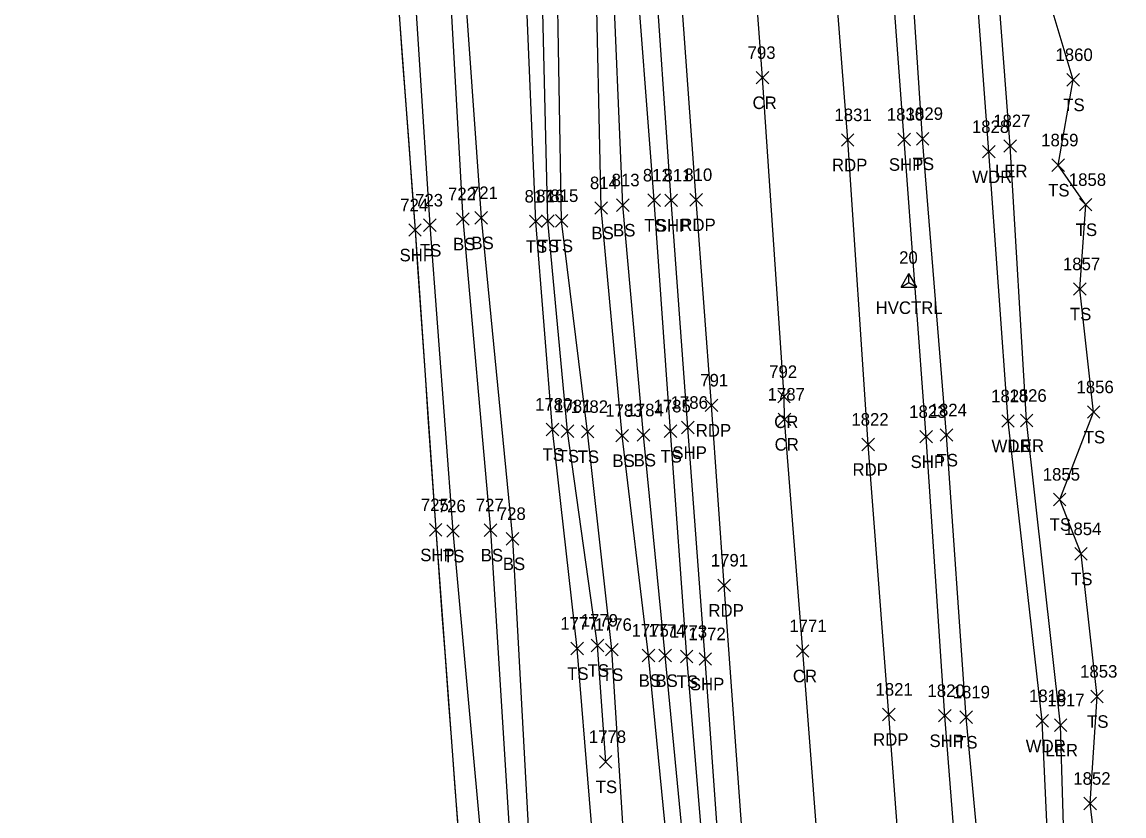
# Model space of a CAD drawing. Extents: x 1650221 to 1650634, y 244606 to 249996.
# Drawn here: x 1650345.8 to 1650521.6, y 244740.5 to 244867.1 of the extents above; entities that cross this region are included whole.
import ezdxf

# ---------------------------------------------------------------- set-up
doc = ezdxf.new("R2010")
doc.units = 0
for name, color, linetype in [('C_A', 7, 'Continuous'), ('C_I', 7, 'Continuous'), ('CPSM', 7, 'Continuous'), ('L_A', 7, 'Continuous'), ('L_I', 7, 'Continuous'), ('L_TIC', 7, 'Continuous'), ('LARO', 7, 'Continuous'), ('LAWA', 7, 'Continuous'), ('LELB', 7, 'Continuous'), ('LSOGP', 7, 'Continuous'), ('P_A', 7, 'Continuous'), ('P_I', 7, 'Continuous'), ('P_TIC', 7, 'Continuous'), ('PET', 7, 'Continuous'), ('PRC', 7, 'Continuous'), ('PSP', 7, 'Continuous')]:
    doc.layers.add(name, color=color, linetype=linetype)

msp = doc.modelspace()

# ---------------------------------------------------------------- linework, layer by layer
at = {"layer": 'CPSM'}
for p, q in [((1650485.99, 244824.86), (1650487.24, 244827.03)), ((1650488.49, 244824.86), (1650487.24, 244827.03)), ((1650487.24, 244825.58), (1650487.24, 244827.03)), ((1650485.99, 244824.86), (1650487.24, 244825.58)), ((1650485.99, 244824.86), (1650488.49, 244824.86)), ((1650487.24, 244825.58), (1650487.24, 244825.58)), ((1650487.24, 244825.58), (1650488.49, 244824.86))]:
    msp.add_line(p, q, dxfattribs=at)
at = {"layer": 'L_TIC'}
for points in [[(1650512.46, 244856.93), (1650514.46, 244858.93)], [(1650514.46, 244856.93), (1650512.46, 244858.93)], [(1650488.44, 244847.53), (1650490.44, 244849.53)], [(1650490.44, 244847.53), (1650488.44, 244849.53)], [(1650502.39, 244846.38), (1650504.39, 244848.38)], [(1650504.39, 244846.38), (1650502.39, 244848.38)], [(1650498.99, 244845.46), (1650500.99, 244847.46)], [(1650500.99, 244845.46), (1650498.99, 244847.46)], [(1650510.05, 244843.32), (1650512.05, 244845.32)], [(1650512.05, 244843.32), (1650510.05, 244845.32)], [(1650440.62, 244836.94), (1650442.62, 244838.94)], [(1650442.62, 244836.94), (1650440.62, 244838.94)], [(1650445.61, 244837.72), (1650447.61, 244839.72)], [(1650447.61, 244837.72), (1650445.61, 244839.72)], [(1650514.45, 244837.01), (1650516.45, 244839.01)], [(1650516.45, 244837.01), (1650514.45, 244839.01)], [(1650437.17, 244836.49), (1650439.17, 244838.49)], [(1650439.17, 244836.49), (1650437.17, 244838.49)], [(1650409.84, 244833.73), (1650411.84, 244835.73)], [(1650411.84, 244833.73), (1650409.84, 244835.73)], [(1650415.09, 244834.73), (1650417.09, 244836.73)], [(1650417.09, 244834.73), (1650415.09, 244836.73)], [(1650418.02, 244834.91), (1650420.02, 244836.91)], [(1650420.02, 244834.91), (1650418.02, 244836.91)], [(1650426.74, 244834.35), (1650428.74, 244836.35)], [(1650428.74, 244834.35), (1650426.74, 244836.35)], [(1650428.64, 244834.41), (1650430.64, 244836.41)], [(1650430.64, 244834.41), (1650428.64, 244836.41)], [(1650430.85, 244834.44), (1650432.85, 244836.44)], [(1650432.85, 244834.44), (1650430.85, 244836.44)], [(1650513.52, 244823.56), (1650515.52, 244825.56)], [(1650515.52, 244823.56), (1650513.52, 244825.56)], [(1650515.72, 244803.93), (1650517.72, 244805.93)], [(1650517.72, 244803.93), (1650515.72, 244805.93)], [(1650502.06, 244802.5), (1650504.06, 244804.5)], [(1650504.06, 244802.5), (1650502.06, 244804.5)], [(1650505.03, 244802.57), (1650507.03, 244804.57)], [(1650507.03, 244802.57), (1650505.03, 244804.57)], [(1650429.39, 244801.16), (1650431.39, 244803.16)], [(1650431.39, 244801.16), (1650429.39, 244803.16)], [(1650431.8, 244800.89), (1650433.8, 244802.89)], [(1650433.8, 244800.89), (1650431.8, 244802.89)], [(1650435, 244800.8), (1650437, 244802.8)], [(1650437, 244800.8), (1650435, 244802.8)], [(1650440.52, 244800.17), (1650442.52, 244802.17)], [(1650442.52, 244800.17), (1650440.52, 244802.17)], [(1650443.9, 244800.26), (1650445.9, 244802.26)], [(1650445.9, 244800.26), (1650443.9, 244802.26)], [(1650448.21, 244800.88), (1650450.21, 244802.88)], [(1650450.21, 244800.88), (1650448.21, 244802.88)], [(1650492.25, 244800.26), (1650494.25, 244802.26)], [(1650494.25, 244800.26), (1650492.25, 244802.26)], [(1650510.3, 244789.99), (1650512.3, 244791.99)], [(1650512.3, 244789.99), (1650510.3, 244791.99)], [(1650413.52, 244784.95), (1650415.52, 244786.95)], [(1650415.52, 244784.95), (1650413.52, 244786.95)], [(1650419.51, 244785.1), (1650421.51, 244787.1)], [(1650421.51, 244785.1), (1650419.51, 244787.1)], [(1650423.03, 244783.72), (1650425.03, 244785.72)], [(1650425.03, 244783.72), (1650423.03, 244785.72)], [(1650513.71, 244781.3), (1650515.71, 244783.3)], [(1650515.71, 244781.3), (1650513.71, 244783.3)], [(1650436.59, 244766.7), (1650438.59, 244768.7)], [(1650438.59, 244766.7), (1650436.59, 244768.7)], [(1650433.33, 244766.21), (1650435.33, 244768.21)], [(1650435.33, 244766.21), (1650433.33, 244768.21)], [(1650433.33, 244766.21), (1650435.33, 244768.21)], [(1650435.33, 244766.21), (1650433.33, 244768.21)], [(1650438.86, 244766.03), (1650440.86, 244768.03)], [(1650440.86, 244766.03), (1650438.86, 244768.03)], [(1650444.7, 244765.1), (1650446.7, 244767.1)], [(1650446.7, 244765.1), (1650444.7, 244767.1)], [(1650447.37, 244765.08), (1650449.37, 244767.08)], [(1650449.37, 244765.08), (1650447.37, 244767.08)], [(1650450.8, 244764.92), (1650452.8, 244766.92)], [(1650452.8, 244764.92), (1650450.8, 244766.92)], [(1650516.26, 244758.56), (1650518.26, 244760.56)], [(1650518.26, 244758.56), (1650516.26, 244760.56)], [(1650495.37, 244755.26), (1650497.37, 244757.26)], [(1650497.37, 244755.26), (1650495.37, 244757.26)], [(1650507.53, 244754.66), (1650509.53, 244756.66)], [(1650509.53, 244754.66), (1650507.53, 244756.66)], [(1650510.45, 244753.99), (1650512.45, 244755.99)], [(1650512.45, 244753.99), (1650510.45, 244755.99)], [(1650437.88, 244748.14), (1650439.88, 244750.14)], [(1650439.88, 244748.14), (1650437.88, 244750.14)], [(1650515.17, 244741.48), (1650517.17, 244743.48)], [(1650517.17, 244741.48), (1650515.17, 244743.48)]]:
    msp.add_lwpolyline(points, dxfattribs=at)
at = {"layer": 'LARO'}
msp.add_lwpolyline([(1650518.65, 244690.58), (1650512.53, 244717.67), (1650511.45, 244754.99), (1650506.03, 244803.57), (1650503.39, 244847.38), (1650499.94, 244892.94), (1650496.08, 244933.34), (1650493.78, 244980.84), (1650496.92, 245008.36), (1650497.83, 245048.46), (1650495.91, 245077.72), (1650494.78, 245118.42), (1650491, 245121.86), (1650493.61, 245139.73)], dxfattribs=at)
at = {"layer": 'LAWA'}
msp.add_lwpolyline([(1650532.93, 244639.7), (1650524.86, 244673.45), (1650514.54, 244690.35), (1650510.25, 244717.67), (1650508.53, 244755.66), (1650503.06, 244803.5), (1650499.99, 244846.46), (1650496.47, 244893.78), (1650492.54, 244932.91), (1650488.72, 244979.52), (1650493.15, 245007.74), (1650492.82, 245049.31), (1650491.93, 245077.75), (1650491, 245121.86)], dxfattribs=at)
at = {"layer": 'LELB'}
for points in [[(1650349.13, 245703.09), (1650351.39, 245660.59), (1650355.99, 245608.05), (1650358.47, 245560.96), (1650362.91, 245508.7), (1650365.76, 245471.06), (1650369.41, 245419.53), (1650373.04, 245367.18), (1650376.89, 245316.29), (1650379.01, 245269.77), (1650383.48, 245220.96), (1650387.1, 245168.26), (1650390.97, 245118.17), (1650394.99, 245063.19), (1650398.03, 245017.1), (1650401.94, 244967.25), (1650403.81, 244936.86), (1650407.34, 244889.23), (1650410.84, 244834.73), (1650414.52, 244785.95), (1650419.34, 244732.83), (1650422.93, 244682.99), (1650426.36, 244632.18), (1650427.51, 244611.7)], [(1650355.71, 245703.22), (1650358.45, 245660.47), (1650361.92, 245609.02), (1650362.95, 245561.76), (1650366.97, 245508.68), (1650370.97, 245471.38), (1650374.07, 245419.38), (1650376.64, 245367.03), (1650382.18, 245316.08), (1650385.68, 245270.43), (1650388.77, 245221.07), (1650390.77, 245168.69), (1650394.69, 245118), (1650401.29, 245063.19), (1650403.89, 245017.69), (1650406.99, 244966.96), (1650408.31, 244937.61), (1650413.12, 244889.16), (1650416.09, 244835.73), (1650420.51, 244786.1), (1650423.8, 244733.3), (1650426.51, 244682.57), (1650434.12, 244632.73), (1650437.01, 244612.78)], [(1650458.26, 244631.23), (1650456.79, 244671.65), (1650452.78, 244720.4), (1650448.37, 244766.08), (1650444.9, 244801.26), (1650441.62, 244837.94), (1650439.87, 244879.23), (1650437.68, 244923.9), (1650433.87, 244972.21), (1650429.49, 245017.89), (1650426.15, 245066.7), (1650422.69, 245123.12), (1650419.86, 245170.84), (1650416.52, 245219.13), (1650411.95, 245271.56), (1650407.71, 245328.35), (1650401.82, 245379.92), (1650396.45, 245433.97), (1650394.84, 245478.56), (1650392.49, 245522.5), (1650389.35, 245551.29), (1650385.12, 245588.75), (1650380.77, 245632.36), (1650373.15, 245685.41)], [(1650462.3, 244631.92), (1650459.1, 244671.43), (1650455.6, 244720.68), (1650451.8, 244765.92), (1650449.21, 244801.88), (1650446.61, 244838.72), (1650443.38, 244880.99), (1650440.04, 244922.8), (1650437.91, 244972.67), (1650433.82, 245018.12), (1650431.01, 245067.65), (1650425.84, 245123.86), (1650424.05, 245171.63), (1650419.6, 245218.92), (1650416.04, 245272.16), (1650411.76, 245328.09), (1650406.63, 245381.03), (1650402.95, 245434.27), (1650400.25, 245479.81), (1650396.41, 245522.79), (1650395.43, 245551.92), (1650392.44, 245589.61), (1650388.27, 245633.5), (1650384.04, 245685.26)], [(1650438.88, 244749.14), (1650437.59, 244767.7), (1650432.8, 244801.89), (1650429.64, 244835.41), (1650428.64, 244877.68), (1650423.48, 244923.01), (1650423.35, 244936.27), (1650423.08, 244949.37), (1650423.3, 244968.5), (1650419.67, 244981.26), (1650420.71, 245016.76), (1650415.5, 245052.76), (1650413.6, 245072.27), (1650415.28, 245100.97), (1650413.57, 245134.68), (1650410.33, 245167.49), (1650406.45, 245196.84), (1650403.51, 245234.02), (1650401.64, 245258.7)], [(1650505.23, 244636.62), (1650502.16, 244675.85), (1650500.4, 244713.01), (1650496.37, 244756.26), (1650493.25, 244801.26), (1650489.44, 244848.53), (1650486.4, 244894.8), (1650483.54, 244931.88), (1650480.85, 244978.69), (1650478.22, 245009.62), (1650475.38, 245046.82), (1650473.75, 245078.48), (1650471.05, 245115.28), (1650468.74, 245140.33)], [(1650434.33, 244767.21), (1650430.39, 244802.16), (1650427.74, 244835.35), (1650426.01, 244877.24), (1650422.68, 244922.99), (1650421.38, 244936.36), (1650420.65, 244948.84), (1650420.12, 244967.21), (1650417.56, 244979.95), (1650417.91, 245016.43), (1650412.94, 245053.12), (1650408.99, 245072.61), (1650411.56, 245100.31), (1650410.98, 245134.62)], [(1650447.97, 244696.01), (1650442.83, 244719.93), (1650439.86, 244767.03), (1650436, 244801.8), (1650431.85, 244835.44), (1650431.08, 244878.45), (1650425.94, 244922.68), (1650425.89, 244936.22), (1650425.63, 244949.38), (1650426.44, 244969.3), (1650423.28, 244982.7), (1650423.71, 245016.93), (1650417.3, 245052.81), (1650416.07, 245074.13), (1650417.99, 245100.65), (1650416.66, 245133.49)], [(1650411.89, 244938.28), (1650415.27, 244889.08), (1650419.02, 244835.91), (1650424.03, 244784.72), (1650426.78, 244733.92), (1650430.2, 244682.93), (1650438.75, 244635.57), (1650441.06, 244623.77), (1650451.56, 244623.37), (1650454.31, 244633.1), (1650454.05, 244671.95), (1650450.18, 244720.54), (1650445.7, 244766.1), (1650441.52, 244801.17), (1650438.17, 244837.49), (1650437.28, 244878.95), (1650435.31, 244923.78), (1650434.3, 244938.37)], [(1650524.82, 244692.13), (1650524.3, 244703.21), (1650517.93, 244716.68), (1650518.69, 244721.62), (1650516.17, 244742.48), (1650517.26, 244759.56), (1650514.71, 244782.3), (1650511.3, 244790.99), (1650516.72, 244804.93), (1650514.52, 244824.56), (1650515.45, 244838.01), (1650511.05, 244844.32), (1650513.46, 244857.93), (1650507.41, 244878.18)], [(1650448.06, 244631.15), (1650443.6, 244630.19), (1650440.26, 244672.57), (1650436.77, 244690.62), (1650438.29, 244719.15), (1650434.33, 244767.21)]]:
    msp.add_lwpolyline(points, dxfattribs=at)
at = {"layer": 'LSOGP'}
msp.add_lwpolyline([(1650405.94, 244868.37), (1650406.44, 244861.49), (1650406.95, 244854.61), (1650407.46, 244847.73), (1650407.96, 244840.85), (1650408.47, 244833.97), (1650408.88, 244827.99), (1650409.29, 244822.01), (1650409.7, 244816.03), (1650410.12, 244810.05), (1650410.53, 244804.07), (1650410.94, 244798.09), (1650411.35, 244792.11), (1650411.77, 244786.13), (1650412.27, 244779.38), (1650412.77, 244772.63), (1650413.27, 244765.89), (1650413.78, 244759.14), (1650414.28, 244752.4), (1650414.78, 244745.65), (1650415.29, 244738.9)], dxfattribs=at)
at = {"layer": 'P_TIC'}
for points in [[(1650462.88, 244857.27), (1650464.88, 244859.27)], [(1650464.88, 244857.27), (1650462.88, 244859.27)], [(1650476.49, 244847.34), (1650478.49, 244849.34)], [(1650478.49, 244847.34), (1650476.49, 244849.34)], [(1650485.51, 244847.42), (1650487.51, 244849.42)], [(1650487.51, 244847.42), (1650485.51, 244849.42)], [(1650448.34, 244837.71), (1650450.34, 244839.71)], [(1650450.34, 244837.71), (1650448.34, 244839.71)], [(1650452.3, 244837.79), (1650454.3, 244839.79)], [(1650454.3, 244837.79), (1650452.3, 244839.79)], [(1650407.47, 244832.97), (1650409.47, 244834.97)], [(1650409.47, 244832.97), (1650407.47, 244834.97)], [(1650466.33, 244806.38), (1650468.33, 244808.38)], [(1650468.33, 244806.38), (1650466.33, 244808.38)], [(1650454.76, 244805.01), (1650456.76, 244807.01)], [(1650456.76, 244805.01), (1650454.76, 244807.01)], [(1650466.4, 244802.77), (1650468.4, 244804.77)], [(1650468.4, 244802.77), (1650466.4, 244804.77)], [(1650450.99, 244801.46), (1650452.99, 244803.46)], [(1650452.99, 244801.46), (1650450.99, 244803.46)], [(1650488.99, 244800), (1650490.99, 244802)], [(1650490.99, 244800), (1650488.99, 244802)], [(1650479.76, 244798.76), (1650481.76, 244800.76)], [(1650481.76, 244798.76), (1650479.76, 244800.76)], [(1650410.77, 244785.13), (1650412.77, 244787.13)], [(1650412.77, 244785.13), (1650410.77, 244787.13)], [(1650456.78, 244776.29), (1650458.78, 244778.29)], [(1650458.78, 244776.29), (1650456.78, 244778.29)], [(1650469.31, 244765.82), (1650471.31, 244767.82)], [(1650471.31, 244765.82), (1650469.31, 244767.82)], [(1650453.77, 244764.54), (1650455.77, 244766.54)], [(1650455.77, 244764.54), (1650453.77, 244766.54)], [(1650483.05, 244755.69), (1650485.05, 244757.69)], [(1650485.05, 244755.69), (1650483.05, 244757.69)], [(1650491.99, 244755.49), (1650493.99, 244757.49)], [(1650493.99, 244755.49), (1650491.99, 244757.49)]]:
    msp.add_lwpolyline(points, dxfattribs=at)
at = {"layer": 'PET'}
for points in [[(1650468.61, 244633.66), (1650465.16, 244679.18), (1650461.18, 244730.39), (1650457.78, 244777.29), (1650455.76, 244806.01), (1650453.3, 244838.79), (1650450.33, 244880.04), (1650447.22, 244922.32), (1650443.48, 244972.73), (1650440.49, 245018.18), (1650436.73, 245069.12), (1650432.63, 245123.79), (1650429.44, 245172.68), (1650426.2, 245218.76), (1650422.12, 245272.82), (1650418.28, 245328.28), (1650414.28, 245381.59), (1650410.42, 245434.18), (1650407.03, 245480.26), (1650404.25, 245522.13), (1650401.81, 245552.98), (1650399.16, 245589.27), (1650395.97, 245634.45), (1650392.36, 245685.55)], [(1650493.02, 244636.16), (1650490.06, 244675.27), (1650487.56, 244709.93), (1650484.05, 244756.69), (1650480.76, 244799.76), (1650477.49, 244848.34), (1650473.97, 244894.14), (1650471.41, 244931.35), (1650468.1, 244977.08), (1650466.09, 245009.13), (1650463.32, 245045.8), (1650460.91, 245077.88), (1650458.15, 245114.32), (1650456.62, 245139.84)]]:
    msp.add_lwpolyline(points, dxfattribs=at)
at = {"layer": 'PRC'}
msp.add_lwpolyline([(1650480.45, 244632.95), (1650477.62, 244672.59), (1650473.75, 244722.56), (1650470.31, 244766.82), (1650467.4, 244803.77), (1650467.33, 244807.38), (1650463.88, 244858.27), (1650461.18, 244894.73), (1650457.56, 244949.95), (1650452.93, 245005.14), (1650451.55, 245032.27), (1650447.57, 245085.81), (1650443.28, 245144.22)], dxfattribs=at)
at = {"layer": 'PSP'}
for points in [[(1650345.78, 245703.18), (1650348.63, 245659.65), (1650352.24, 245608.27), (1650356.14, 245560.76), (1650359.83, 245508.67), (1650362.71, 245470.35), (1650366.37, 245419.55), (1650370.09, 245366.17), (1650373.73, 245316.16), (1650376.75, 245269.64), (1650380.21, 245220.67), (1650384.07, 245168.16), (1650387.54, 245117.86), (1650391.85, 245063.26), (1650394.9, 245017.42), (1650398.56, 244967.17), (1650400.8, 244936.49), (1650404.42, 244889.02), (1650408.47, 244833.97), (1650411.77, 244786.13), (1650415.79, 244732.16), (1650419.27, 244682.87), (1650423.02, 244632.43), (1650424.78, 244611.26)], [(1650464.84, 244632.07), (1650461.81, 244671.31), (1650457.94, 244720.75), (1650454.77, 244765.54), (1650451.99, 244802.46), (1650449.34, 244838.71), (1650446.5, 244879.72), (1650443.46, 244922.98), (1650439.98, 244973.19), (1650436.37, 245018.02), (1650433.26, 245068.28), (1650429.09, 245123.84), (1650425.59, 245171.99), (1650422.33, 245218.99), (1650418.38, 245272.19), (1650414.3, 245328), (1650410.4, 245381.3), (1650406.52, 245434.23), (1650403.48, 245480), (1650400.24, 245522.79), (1650398.25, 245552.46), (1650395.41, 245589.43), (1650392.23, 245633.8), (1650388.44, 245685.1)], [(1650502.02, 244636.4), (1650499, 244675.82), (1650496.5, 244711.9), (1650492.99, 244756.49), (1650489.99, 244801), (1650486.51, 244848.42), (1650483.1, 244894.51), (1650480.52, 244931.79), (1650477.17, 244978.41), (1650475.14, 245009.4), (1650472.27, 245046.65), (1650470.2, 245077.93), (1650467.35, 245115.19), (1650465.66, 245140.38)]]:
    msp.add_lwpolyline(points, dxfattribs=at)

# ---------------------------------------------------------------- texts
at = {"layer": 'C_A'}
msp.add_text('HVCTRL', height=2, dxfattribs=at).set_placement((1650481.94, 244820.58))
at = {"layer": 'C_I'}
msp.add_text('20', height=2, dxfattribs=at).set_placement((1650485.69, 244828.58))
at = {"layer": 'L_A'}
for s, p in [('TS', (1650511.87, 244852.93)), ('TS', (1650487.85, 244843.53)), ('LER', (1650500.97, 244842.38)), ('WDR', (1650497.35, 244841.46)), ('TS', (1650509.46, 244839.32)), ('TS', (1650445.02, 244833.72)), ('BS', (1650436.61, 244832.49)), ('BS', (1650440.06, 244832.94)), ('TS', (1650513.86, 244833.01)), ('BS', (1650414.54, 244830.73)), ('BS', (1650417.46, 244830.91)), ('TS', (1650426.14, 244830.35)), ('TS', (1650428.05, 244830.41)), ('TS', (1650430.26, 244830.44)), ('TS', (1650409.25, 244829.73)), ('TS', (1650512.93, 244819.56)), ('WDR', (1650500.43, 244798.5)), ('LER', (1650503.61, 244798.57)), ('TS', (1650515.13, 244799.93)), ('TS', (1650428.8, 244797.16)), ('TS', (1650431.21, 244796.89)), ('TS', (1650434.41, 244796.8)), ('TS', (1650447.62, 244796.88)), ('BS', (1650439.96, 244796.17)), ('BS', (1650443.34, 244796.26)), ('TS', (1650491.66, 244796.26)), ('TS', (1650509.7, 244785.99)), ('TS', (1650412.93, 244780.95)), ('BS', (1650418.95, 244781.1)), ('BS', (1650422.47, 244779.72)), ('TS', (1650513.12, 244777.3)), ('TS', (1650432.74, 244762.21)), ('TS', (1650432.74, 244762.21)), ('TS', (1650436, 244762.7)), ('TS', (1650438.27, 244762.03)), ('BS', (1650444.14, 244761.1)), ('BS', (1650446.81, 244761.08)), ('TS', (1650450.21, 244760.92)), ('TS', (1650515.67, 244754.56)), ('TS', (1650494.78, 244751.26)), ('WDR', (1650505.89, 244750.66)), ('LER', (1650509.03, 244749.99)), ('TS', (1650437.29, 244744.14))]:
    msp.add_text(s, height=2, dxfattribs=at).set_placement(p)
at = {"layer": 'L_I'}
for s, p in [('1860', (1650510.63, 244860.93)), ('1829', (1650486.74, 244851.53)), ('1828', (1650497.3, 244849.46)), ('1827', (1650500.7, 244850.38)), ('1859', (1650508.35, 244847.32)), ('814', (1650436.37, 244840.49)), ('813', (1650439.83, 244840.94)), ('812', (1650444.81, 244841.72)), ('1858', (1650512.76, 244841.01)), ('722', (1650413.73, 244838.73)), ('721', (1650417.23, 244838.91)), ('723', (1650408.47, 244837.73)), ('817', (1650425.94, 244838.35)), ('816', (1650427.79, 244838.41)), ('815', (1650430.05, 244838.44)), ('1857', (1650511.82, 244827.56)), ('1856', (1650513.98, 244807.93)), ('1825', (1650500.37, 244806.5)), ('1826', (1650503.28, 244806.57)), ('1780', (1650427.61, 244805.16)), ('1781', (1650430.67, 244804.89)), ('1782', (1650433.31, 244804.8)), ('1783', (1650438.82, 244804.17)), ('1784', (1650442.2, 244804.26)), ('1785', (1650446.51, 244804.88)), ('1824', (1650490.56, 244804.26)), ('1855', (1650508.6, 244793.99)), ('726', (1650412.1, 244788.95)), ('727', (1650418.15, 244789.1)), ('728', (1650421.67, 244787.72)), ('1854', (1650512.01, 244785.3)), ('1777', (1650431.64, 244770.21)), ('1777', (1650431.64, 244770.21)), ('1779', (1650434.89, 244770.7)), ('1776', (1650437.11, 244770.03)), ('1775', (1650443.01, 244769.1)), ('1774', (1650445.68, 244769.08)), ('1773', (1650449.11, 244768.92)), ('1853', (1650514.56, 244762.56)), ('1819', (1650494.23, 244759.26)), ('1818', (1650506.41, 244758.66)), ('1817', (1650509.32, 244757.99)), ('1778', (1650436.19, 244752.14)), ('1852', (1650513.47, 244745.48))]:
    msp.add_text(s, height=2, dxfattribs=at).set_placement(p)
at = {"layer": 'P_A'}
for s, p in [('CR', (1650462.31, 244853.27)), ('RDP', (1650474.98, 244843.34)), ('SHP', (1650484.05, 244843.42)), ('SHP', (1650446.88, 244833.71)), ('RDP', (1650450.79, 244833.79)), ('SHP', (1650406, 244828.97)), ('CR', (1650465.76, 244802.38)), ('RDP', (1650453.25, 244801.01)), ('CR', (1650465.83, 244798.77)), ('SHP', (1650449.52, 244797.46)), ('RDP', (1650478.25, 244794.76)), ('SHP', (1650487.52, 244796)), ('SHP', (1650409.3, 244781.13)), ('RDP', (1650455.27, 244772.29)), ('CR', (1650468.74, 244761.82)), ('SHP', (1650452.31, 244760.54)), ('RDP', (1650481.54, 244751.69)), ('SHP', (1650490.53, 244751.49))]:
    msp.add_text(s, height=2, dxfattribs=at).set_placement(p)
at = {"layer": 'P_I'}
for s, p in [('793', (1650461.52, 244861.27)), ('1831', (1650475.37, 244851.34)), ('1830', (1650483.73, 244851.42)), ('811', (1650448.11, 244841.71)), ('810', (1650451.42, 244841.79)), ('724', (1650406.11, 244836.97)), ('791', (1650453.96, 244809.01)), ('792', (1650464.96, 244810.38)), ('1786', (1650449.24, 244805.46)), ('1787', (1650464.71, 244806.77)), ('1823', (1650487.3, 244804)), ('1822', (1650478.07, 244802.76)), ('725', (1650409.4, 244789.13)), ('1791', (1650455.65, 244780.29)), ('1772', (1650452.08, 244768.54)), ('1771', (1650468.18, 244769.82)), ('1821', (1650481.92, 244759.69)), ('1820', (1650490.21, 244759.49))]:
    msp.add_text(s, height=2, dxfattribs=at).set_placement(p)

doc.saveas('drawing.dxf')
